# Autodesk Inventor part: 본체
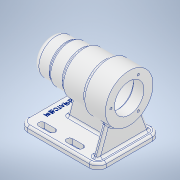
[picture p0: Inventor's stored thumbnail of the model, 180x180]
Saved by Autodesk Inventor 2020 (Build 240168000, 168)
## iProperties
Created: 2021-10
Part Number: 본체
Material: 알루미늄 6061
Document SubType Name: Modeling
Designer: user
Density: 2.7 g/cm^3
Appearance: 알루미늄 - 평지
Mass: 693.332 g
Surface Area: 699.488 cm^2
Volume: 256.79 cm^3
Author: user
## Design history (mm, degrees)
sketch "스케치1"
  geometry: L1 (0, 0)-(0, 34); L2 (0, 34)-(-32, 34); L3 (-32, 34)-(-32, 30); L4 (-32, 30)-(-66, 30); L5 (-66, 30)-(-66, 27); L6 (-66, 27)-(-88, 27); L7 (-88, 27)-(-88, 25); L8 (-88, 25)-(-112, 25); L9 (-112, 25)-(-112, 0); L10 (-112, 0)-(0, 0)
  constraints: 20 end point, 9 perpendicular, 1 vertical
  dimensions: "d0" = 34 distance of L1.start L1.end; "d1" = 112 distance of L9.end L1.start; "d2" = 24 distance between parallel lines of L9 L7; "d4" = 46 distance between parallel lines of L9 L5; "d5" = 80 distance between parallel lines of L9 L3; "d6" = 60 diameter of L4 L10; "d7" = 54 diameter of L6 L10; "d8" = 50 diameter of L8 L10
revolve "회전1" sketch "스케치1" stored, may be unused: angle "d9" = 90 deg
fillet "모깎기1" dims "d10" = 8
sketch "스케치2"
  geometry: C1 r 21 at (0, 0); 1 further point
  constraints: 1 centre point, 1 coincident
  dimensions: "d11" = 42 diameter of C1
extrude "돌출1" cut sketch "스케치2" distance "d12" = 15; taper "d13" = 0 deg
sketch "스케치3"
  geometry: C1 r 24 at (0, 0); 1 further point
  constraints: 1 centre point, 1 coincident
  dimensions: "d14" = 48 diameter of C1
extrude "돌출2" cut sketch "스케치3" distance "d15" = 54; taper "d16" = 0 deg
sketch "스케치4"
  geometry: C1 r 21 at (0, 0); 1 further point
  constraints: 1 centre point, 1 coincident
  dimensions: "d17" = 42 diameter of C1
extrude "돌출3" cut sketch "스케치4" distance "d18" = 12; taper "d19" = 0 deg
sketch "스케치5"
  geometry: C1 r 17.5 at (0, 0); 1 further point
  constraints: 1 centre point, 1 coincident
  dimensions: "d20" = 35 diameter of C1
extrude "돌출4" cut sketch "스케치5" distance "d21" = 18; taper "d22" = 0 deg
sketch "스케치6"
  geometry: C1 r 16 at (0, 0); 1 further point
  constraints: 1 centre point, 1 coincident
  dimensions: "d23" = 32 diameter of C1
extrude "돌출5" cut sketch "스케치6" distance "d24" = 4; taper "d25" = 0 deg
sketch "스케치7"
  geometry: C1 r 10.5 at (0, 0); 1 further point
  constraints: 1 centre point, 1 coincident
  dimensions: "d26" = 21 diameter of C1
extrude "돌출6" cut sketch "스케치7" distance "d27" = 3; taper "d28" = 0 deg
fillet "모깎기2" dims "d29" = 0.3
fillet "모깎기3" dims "d30" = 3
sketch "스케치8"
  geometry: 2 further points
  constraints: 1 horizontal alignment
  dimensions: "d31" = 26 distance of point (-26, 0) point (0, 0)
hole "구멍1" sketch "스케치8" at (-26, 0) diameter "d32" = 3.242; stored, may be unused: countersink angle "d36" = 90 deg, drill point angle "d38" = 118 deg; dims "d33" = 8, "d34" = 4, "d35" = 2, "d37" = 11
node "작업 평면1"
sketch "스케치9"
  geometry: L1 (112, -45)-(0, -45); L2 (0, -45)-(0, 45); L3 (0, 45)-(112, 45); L4 (112, 45)-(112, -45); 2 further points
  constraints: 8 end point, 2 midpoint, 2 parallel, 1 horizontal, 1 horizontal alignment, 1 perpendicular
  dimensions: "d43" = 112 distance of L2.end L3.end; "d44" = 90 distance of L1.end L2.end
extrude "돌출7" join sketch "스케치9" distance "d45" = 8; taper "d46" = 0 deg
fillet "모깎기4" dims "d47" = 12
sketch "스케치10"
  geometry: L1 (-8, 4)-(-85, 4); L2 (-85, 4)-(-85, -4); L3 (-85, -4)-(-8, -4); L4 (-8, -4)-(-8, 4); L5 (-8, 4)-(-85, -4); L6 (-85, 4)-(-8, -4); L7 (0, -33)-(0, 33) reference; 4 further points
  constraints: 12 end point, 4 midpoint, 2 parallel, 1 horizontal, 1 horizontal alignment, 1 perpendicular
  dimensions: "d48" = 8 distance between parallel lines of L7 L4; "d49" = 8 distance of L3.end L1.start; "d50" = 77 distance of L1.start L1.end
extrude "돌출8" join sketch "스케치10" stored distance "d51" = 8; taper "d52" = 0 deg
feature "면 기울기1" dims angle "d53" = 15 deg
sketch "스케치11"
  geometry: L1 (-19.409, 37.342)-(-33, 0); L2 (27.409, 37.342)-(41, 0); L3 (-41, 0)-(-41, -8) reference; L4 (49, -8)-(49, 0) reference; L5 (-41, 0)-(-29, 0) reference; L6 (37, 0)-(49, 0) reference; L7 (37, 0)-(-29, 0) reference; L8 (0, 0)-(0, 28.236) reference; L9 (-29, 0)-(37, 0) reference; L10 (-41, 0)-(-29, 0) reference; L11 (8, 0)-(8, 28.236) reference; L12 (37, 0)-(49, 0) reference; A1 r 34 centre (4, 62) between (8, 28.236) and (0, 28.236) reference; 2 further points
  constraints: 4 end point, 2 point on circle, 2 point on line
  dimensions: "d54" = 8 distance from line of L3 L1.end; "d55" = 8 distance from line of L4 L2.end; "d56" = 110 deg angle of L5 L1; "d57" = 110 deg angle of L6 L2
extrude "돌출9" join sketch "스케치11" distance "d58" = 8; taper "d59" = 0 deg
sketch "스케치12"
  geometry: L1 (-92, 33)-(-77, 33); L2 (-92, 28.5)-(-77, 28.5); L3 (-77, 37.5)-(-92, 37.5); L4 (-112, 33)-(-112, -33) reference; L5 (-52, 33)-(-37, 33); L6 (-52, 28.5)-(-37, 28.5); L7 (-37, 37.5)-(-52, 37.5); A1 r 4.5 centre (-92, 33) between (-92, 37.5) and (-92, 28.5); A2 r 4.5 centre (-77, 33) between (-77, 28.5) and (-77, 37.5); A3 r 4.5 centre (-37, 33) between (-37, 28.5) and (-37, 37.5); A4 r 4.5 centre (-52, 33) between (-52, 37.5) and (-52, 28.5); 3 further points
  constraints: 16 end point, 8 point on circle, 8 tangent, 4 centre point, 2 horizontal, 2 midpoint, 2 parallel, 1 horizontal alignment
  dimensions: "d60" = 4.5 radius of A1; "d61" = 20 distance from line of L4 L1.start; "d62" = 15 distance of L1.start L1.end; "d63" = 33 vertical distance of point (0, 0) point (-84.5, 33); "d66" = 4.5 radius of A4; "d67" = 15 distance of L5.start L5.end; "d68" = 25 distance of L1.end L5.start
extrude "돌출10" cut sketch "스케치12" extent not by distance; stored distance "d64" = 74.369; taper "d65" = 0 deg
fillet "모깎기5" dims "d69" = 3
fillet "모깎기6" dims "d70" = 3
fillet "모깎기7" dims "d71" = 3
fillet "모깎기8" dims "d72" = 3
sketch "스케치13"
  geometry: L1 (-112, 33)-(-112, -33) reference; 2 further points
  constraints: 1 horizontal alignment, 1 other
  dimensions: "d73" = 12 distance from line of L1 point (-100, 0)
feature "엠보싱1" sketch "스케치13" dims "d74" = 0.5, "d75" = 0
node "솔리드1"
pattern_circular "원형 패턴1" dims angle "d40" = 360 deg
mirror "미러1"
feature "A9D066F2-1C7D-4E18-AEED-F7BC21143FA4" dims "d32" = 3.242, "d33" = 8, "d34" = 4, "d35" = 2, "d36" = 90 deg, "d37" = 11, "d38" = 118 deg
